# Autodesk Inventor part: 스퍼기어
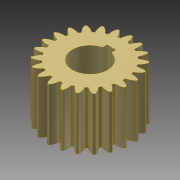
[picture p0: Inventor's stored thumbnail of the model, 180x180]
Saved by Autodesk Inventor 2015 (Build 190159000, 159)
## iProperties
Created: 2023-11
Part Number: 스퍼기어
Material: 알루미늄 6061
Document SubType Name: Modeling
Designer: mdu-01
Density: 1 g/cm^3
Appearance: 알루미늄 - 평지(1)
Author: mdu-01
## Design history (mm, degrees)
sketch "스케치1" dims "d2" = 44, "d5" = 2.5
  geometry: L1 (-2.5, 9.682)-(2.5, 9.682); L2 (2.5, 9.682)-(2.5, 12.3); L3 (2.5, 12.3)-(-2.5, 12.3); L4 (-2.5, 12.3)-(-2.5, 9.682); L5 (0, 0)-(0, 9.682); A1 r 10 centre (0, 0) between (-2.5, 9.682) and (2.5, 9.682); A2 r 24 centre (0, 0) between (0.57, 23.993) and (-0.57, 23.993); A3 r 9.393 centre (-7.31, 18.88) between (2.07, 19.39) and (0.57, 23.993); A4 r 9.393 centre (7.31, 18.88) between (-0.57, 23.993) and (-2.07, 19.39); A5 r 19.5 centre (0, 0) between (2.07, 19.39) and (-2.07, 19.39); 2 further points
  constraints: 11 point on circle, 10 end point, 5 centre point, 3 coincident, 3 symmetric about line, 2 parallel, 1 horizontal, 1 midpoint, 1 perpendicular, 7 other
  dimensions: "d0" = 20 diameter of A1; "d3" = 5 distance between parallel lines of L2 L4; "d4" = 2.3 distance edge to line of A1 L3; "d6" = 2 dimension on A2; "d7" = 1.57 horizontal distance of point (1.57, 21.944) L5.start; "d8" = 1 horizontal distance of A2.start point (1.57, 21.944); "d9" = 0.5 horizontal distance of point (1.57, 21.944) A3.start
extrude "돌출1" new body sketch "스케치1" distance "d10" = 30; taper "d11" = 0 deg
extrude "돌출2" join sketch "스케치1" distance "d12" = 30; taper "d13" = 0 deg
fillet "모깎기1" dims "d14" = 0.25
node "솔리드1"
pattern_circular "원형 패턴1" dims angle "d16" = 360 deg
